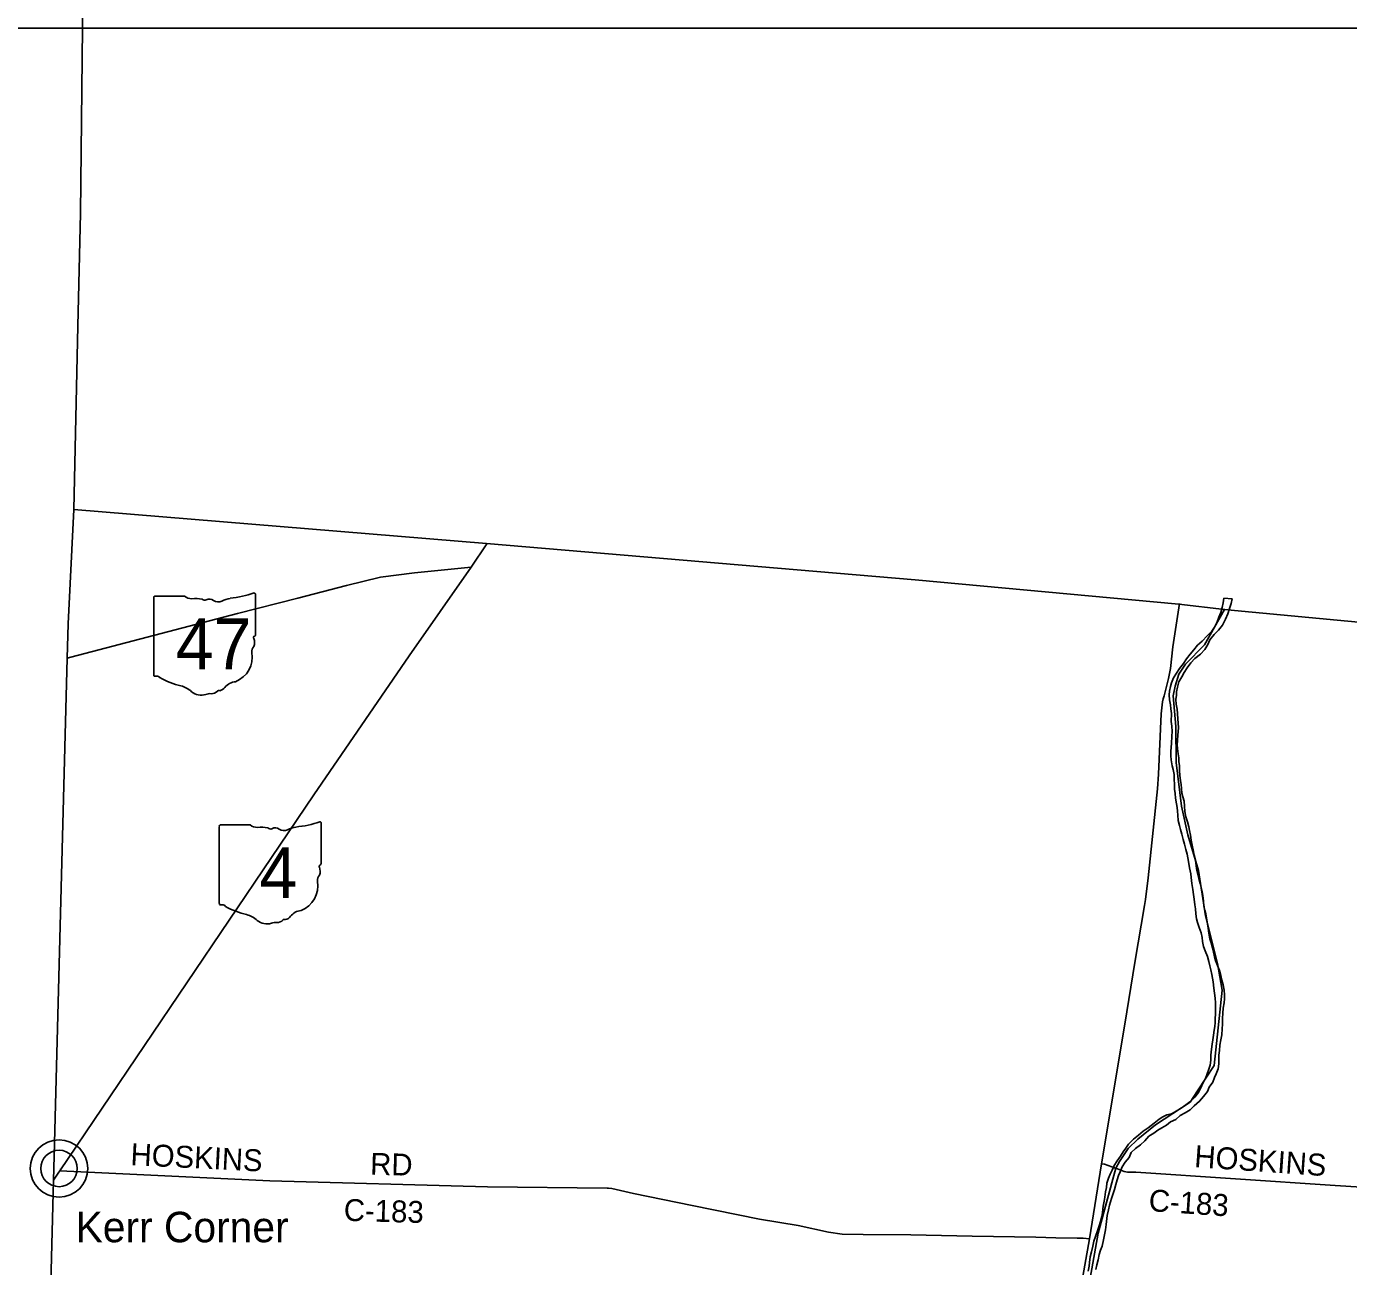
# Model space of a CAD drawing. Extents: x 1674899 to 2057726, y 653888 to 988278.
# Drawn here: x 1759512 to 1777590, y 880687 to 897649 of the extents above; entities that cross this region are included whole.
import ezdxf

# ---------------------------------------------------------------- set-up
doc = ezdxf.new("R2010")
doc.units = 0
for name, color, linetype in [('GM_X_Adjacent_County', 7, 'Continuous'), ('GM_X_County', 7, 'Continuous'), ('GM_X_County_Road', 7, 'Continuous'), ('GM_X_County_Road_Text', 7, 'Continuous'), ('GM_X_Major_River', 7, 'Continuous'), ('GM_X_State_Location', 7, 'Continuous'), ('GM_X_State_Route', 7, 'Continuous'), ('GM_X_State_Shield', 7, 'Continuous'), ('GM_X_Township', 7, 'Continuous'), ('GM_X_Unincorporated', 7, 'Continuous'), ('GM_X_Unincorporated_Location', 7, 'Continuous'), ('GM_X_Unincorporated_Text', 7, 'Continuous'), ('SH_Named_Boundary', 7, 'Continuous')]:
    doc.layers.add(name, color=color, linetype=linetype)

msp = doc.modelspace()

# ---------------------------------------------------------------- linework, layer by layer
at = {"layer": 'GM_X_Adjacent_County'}
for points in [[(1758493, 914019), (1759934, 914025), (1760358, 914021), (1760364, 911751), (1760364, 911476), (1760357, 909471), (1760334, 904783), (1760318, 901515), (1760281, 898058), (1760249, 895094), (1760215, 893547), (1760161, 891042), (1760084, 889480), (1760071, 889009), (1759886, 882027), (1759881, 881868), (1759795, 878524), (1759745, 876009), (1759690, 868390), (1759631, 865937), (1759615, 862978)], [(1778209, 889456), (1776032, 889658), (1775894, 889674), (1775269, 889747), (1771666, 890080), (1765804, 890577), (1760161, 891042), (1760215, 893547), (1760249, 895094), (1760281, 898058), (1760318, 901515), (1760334, 904783), (1760357, 909471), (1760364, 911476), (1760364, 911751), (1760358, 914021), (1759934, 914025), (1758493, 914019)]]:
    msp.add_lwpolyline(points, dxfattribs=at)
at = {"layer": 'GM_X_County'}
msp.add_lwpolyline([(1759615, 862978), (1759631, 865937), (1759690, 868390), (1759745, 876009), (1759795, 878524), (1759881, 881868), (1759886, 882027), (1760071, 889009), (1760084, 889480), (1760161, 891042), (1765804, 890577), (1771666, 890080), (1775269, 889747), (1775894, 889674), (1776032, 889658), (1778209, 889456)], dxfattribs=at)
at = {"layer": 'GM_X_County_Road'}
for points in [[(1774211, 882090), (1774252, 882089), (1774404, 882033)], [(1774404, 882033), (1774406, 882032), (1774523, 881989), (1774565, 881978), (1774598, 881976), (1774681, 881977), (1777408, 881796), (1778560, 881723), (1779427, 881668), (1779984, 881633), (1780423, 881605), (1780749, 881582)], [(1759969, 881997), (1762841, 881858), (1765814, 881778), (1767451, 881759), (1767471, 881758), (1767516, 881753), (1767813, 881684), (1768617, 881522), (1769536, 881337), (1770062, 881247), (1770477, 881159), (1770666, 881130), (1770953, 881125), (1771606, 881121), (1772443, 881104), (1773313, 881088), (1773587, 881081), (1773877, 881076), (1773962, 881074), (1774048, 881064)]]:
    msp.add_lwpolyline(points, dxfattribs=at)
at = {"layer": 'GM_X_Major_River'}
msp.add_line((1775884, 889829), (1775997, 889820), dxfattribs=at)
for points in [[(1775884, 889829), (1775875, 889767), (1775863, 889701), (1775842, 889635), (1775817, 889569), (1775795, 889507), (1775764, 889444), (1775720, 889378), (1775655, 889313), (1775588, 889243), (1775526, 889184), (1775473, 889124), (1775423, 889063), (1775376, 888999), (1775334, 888934), (1775279, 888868), (1775236, 888803), (1775196, 888737), (1775167, 888671), (1775155, 888619), (1775142, 888557), (1775137, 888507), (1775141, 888439), (1775154, 888371), (1775161, 888313), (1775167, 888250), (1775166, 888144), (1775173, 888080), (1775176, 888006), (1775175, 887940), (1775170, 887840), (1775166, 887790), (1775159, 887730), (1775159, 887672), (1775166, 887618), (1775177, 887537), (1775193, 887487), (1775204, 887415), (1775207, 887347), (1775208, 887283), (1775212, 887215), (1775217, 887156), (1775222, 887092), (1775237, 887016), (1775247, 886966), (1775252, 886914), (1775256, 886862), (1775261, 886789), (1775276, 886721), (1775290, 886667), (1775309, 886601), (1775330, 886530), (1775347, 886466), (1775363, 886392), (1775382, 886327), (1775391, 886275), (1775407, 886199), (1775416, 886141), (1775433, 886057), (1775438, 886006), (1775448, 885928), (1775459, 885846), (1775470, 885776), (1775481, 885712), (1775490, 885633), (1775496, 885579), (1775501, 885511), (1775512, 885445), (1775524, 885391), (1775549, 885324), (1775574, 885252), (1775587, 885188), (1775595, 885131), (1775608, 885063), (1775629, 885005), (1775659, 884927), (1775678, 884858), (1775693, 884802), (1775707, 884746), (1775720, 884682), (1775729, 884631), (1775737, 884581), (1775746, 884493), (1775764, 884357), (1775770, 884294), (1775771, 884226), (1775772, 884142), (1775767, 884076), (1775765, 884026), (1775760, 883972), (1775754, 883918), (1775745, 883852), (1775734, 883788), (1775724, 883730), (1775715, 883658), (1775708, 883580), (1775707, 883508), (1775699, 883442), (1775678, 883388), (1775657, 883322), (1775635, 883257)], [(1775997, 889820), (1775985, 889754), (1775964, 889688), (1775940, 889616), (1775905, 889542), (1775868, 889461), (1775812, 889393), (1775753, 889330), (1775692, 889260), (1775664, 889194), (1775623, 889129), (1775564, 889063), (1775490, 889002), (1775433, 888943), (1775381, 888875), (1775342, 888811), (1775310, 888752), (1775269, 888686), (1775250, 888612), (1775236, 888550), (1775235, 888500), (1775229, 888444), (1775234, 888380), (1775247, 888310), (1775253, 888252), (1775256, 888173), (1775261, 888123), (1775264, 888055), (1775258, 888003), (1775257, 887953), (1775253, 887883), (1775248, 887821), (1775251, 887771), (1775261, 887701), (1775268, 887647), (1775270, 887594), (1775277, 887534), (1775280, 887476), (1775281, 887402), (1775293, 887336), (1775302, 887282), (1775306, 887226), (1775311, 887163), (1775322, 887113), (1775340, 887053), (1775345, 886985), (1775350, 886909), (1775365, 886836), (1775389, 886768), (1775404, 886702), (1775413, 886652), (1775427, 886585), (1775438, 886519), (1775453, 886449), (1775464, 886385), (1775480, 886312), (1775499, 886244), (1775504, 886170), (1775517, 886106), (1775529, 886049), (1775542, 885993), (1775559, 885927), (1775573, 885873), (1775586, 885817), (1775596, 885764), (1775605, 885686), (1775612, 885616), (1775623, 885562), (1775637, 885510), (1775646, 885451), (1775663, 885375), (1775671, 885313), (1775678, 885245), (1775695, 885170), (1775712, 885116), (1775730, 885048), (1775745, 884988), (1775758, 884925), (1775772, 884873), (1775826, 884736), (1775845, 884666), (1775859, 884606), (1775876, 884538), (1775887, 884469), (1775892, 884403), (1775892, 884349), (1775887, 884295), (1775877, 884219), (1775872, 884153), (1775867, 884079), (1775866, 884001), (1775862, 883937), (1775857, 883857), (1775842, 883789), (1775829, 883713), (1775823, 883641), (1775818, 883577), (1775815, 883513), (1775815, 883459), (1775806, 883391), (1775781, 883325)], [(1775781, 883325), (1775757, 883271), (1775732, 883207), (1775685, 883140), (1775661, 883080), (1775606, 883011), (1775552, 882947), (1775481, 882884), (1775423, 882832), (1775354, 882791), (1775286, 882752), (1775228, 882700), (1775157, 882665), (1775101, 882621), (1775035, 882582), (1774981, 882551), (1774926, 882513), (1774860, 882472), (1774803, 882408), (1774745, 882351), (1774678, 882302), (1774618, 882246), (1774591, 882180), (1774537, 882115), (1774496, 882051), (1774466, 881984), (1774445, 881932), (1774428, 881872), (1774406, 881808), (1774391, 881742), (1774369, 881684), (1774348, 881618), (1774323, 881528), (1774308, 881463), (1774291, 881387), (1774276, 881261), (1774265, 881189), (1774251, 881119), (1774238, 881053), (1774219, 880965), (1774199, 880911), (1774182, 880851), (1774165, 880779), (1774147, 880711), (1774134, 880645)], [(1775635, 883257), (1775602, 883203), (1775570, 883131), (1775537, 883067), (1775486, 883002), (1775418, 882940), (1775366, 882899), (1775301, 882854), (1775233, 882810), (1775169, 882777), (1775103, 882760), (1775050, 882734), (1775000, 882701), (1774930, 882647), (1774851, 882584), (1774783, 882537), (1774716, 882483), (1774648, 882430), (1774581, 882361), (1774543, 882307), (1774506, 882255), (1774470, 882198), (1774427, 882132), (1774387, 882068), (1774356, 882005), (1774331, 881951), (1774309, 881897), (1774286, 881829), (1774278, 881767), (1774267, 881707), (1774258, 881637), (1774246, 881583), (1774235, 881511), (1774226, 881427), (1774215, 881373), (1774199, 881304), (1774178, 881246), (1774157, 881176), (1774129, 881098), (1774108, 881032), (1774095, 880964), (1774077, 880886), (1774056, 880818), (1774047, 880744), (1774041, 880690), (1774028, 880625)]]:
    msp.add_lwpolyline(points, dxfattribs=at)
at = {"layer": 'GM_X_State_Route'}
for points in [[(1759881, 881868), (1759956, 881980), (1759969, 881997), (1763443, 887141), (1764744, 889038), (1765591, 890255), (1765808, 890573)], [(1760071, 889009), (1760118, 889022), (1762397, 889618), (1763225, 889831), (1763889, 890004), (1764355, 890118), (1764820, 890175), (1765591, 890255)], [(1773882, 880140), (1774048, 881064), (1774211, 882090), (1774530, 884003), (1774667, 884846), (1774801, 885624), (1774814, 885707), (1774851, 886003), (1774976, 887219), (1774992, 887423), (1775028, 888248), (1775030, 888289), (1775035, 888331), (1775040, 888372), (1775048, 888413), (1775057, 888454), (1775067, 888494), (1775128, 888732), (1775139, 888776), (1775154, 888865), (1775187, 889163), (1775276, 889757)]]:
    msp.add_lwpolyline(points, dxfattribs=at)
at = {"layer": 'GM_X_State_Shield'}
for p, q in [((1761252, 889837), (1761252, 888780)), ((1761673, 889855), (1761266, 889855)), ((1762644, 889328), (1762644, 889881)), ((1762644, 889329), (1762644, 889328)), ((1762571, 886727), (1762163, 886727)), ((1763542, 886200), (1763542, 886753)), ((1762149, 886708), (1762149, 885652)), ((1763542, 886200), (1763542, 886200))]:
    msp.add_line(p, q, dxfattribs=at)
for centre, radius, start, end in [((1761268, 889839), 16.1, 98.1301, 188.1301), ((1761770, 889978), 156, 231.6195, 271.1119), ((1761822, 889262), 562, 80.4867, 94.9883), ((1761950, 889845), 45.1, 219.7921, 297.1024), ((1762016, 889722), 93.8, 54.4667, 119.1411), ((1762137, 889890), 113, 233.8562, 294.8282), ((1762336, 889532), 297, 97.3462, 120.7689), ((1762148, 891296), 1476, 275.8445, 288.9065), ((1762629, 889883), 15.5, 351.8621, 97.738), ((1762640, 889288), 24, 107.944, 210.337), ((1762488, 889218), 144, 340.033, 23.6496), ((1762628, 889326), 16.6, 289.6038, 7.7341), ((1762231, 889027), 369, 292.3089, 8.9858), ((1762700, 889097), 105, 136.8065, 186.9296), ((1761268, 888778), 16.3, 171.9584, 258.3066), ((1761270, 888886), 124, 267.339, 280.6039), ((1761296, 888719), 44.8, 29.7484, 93.2717), ((1761861, 889669), 1066, 240.4129, 257.1985), ((1761543, 888305), 334, 47.1842, 75.836), ((1761904, 888714), 212, 230.7004, 286.2918), ((1762042, 888635), 113, 268.777, 315.5493), ((1762144, 888533), 31.8, 65.7517, 132.6484), ((1762130, 888678), 119, 282.8732, 323.2771), ((1762387, 888484), 202, 94.4031, 142.5768), ((1762026, 888349), 174, 85.6951, 111.2099), ((1762165, 886711), 16.1, 98.1301, 188.1301), ((1762668, 886849), 156, 231.6195, 271.1119), ((1763046, 888167), 1476, 275.8445, 288.9065), ((1763526, 886755), 15.5, 351.8621, 97.738), ((1762720, 886133), 562, 80.4867, 94.9883), ((1762847, 886716), 45.1, 219.7921, 297.1024), ((1762914, 886594), 93.8, 54.4667, 119.1411), ((1763035, 886762), 113, 233.8562, 294.8282), ((1763234, 886404), 297, 97.3462, 120.7689), ((1763538, 886159), 24, 107.944, 210.337), ((1763525, 886198), 16.6, 289.6038, 7.7341), ((1763597, 885969), 105, 136.8065, 186.9296), ((1763385, 886090), 144, 340.033, 23.6496), ((1763128, 885898), 369, 292.3089, 8.9858), ((1762166, 885649), 16.3, 171.9584, 258.3066), ((1762168, 885758), 124, 267.339, 280.6039), ((1762193, 885591), 44.8, 29.7484, 93.2717), ((1762759, 886540), 1066, 240.4129, 257.1985), ((1762441, 885177), 334, 47.1842, 75.836), ((1763028, 885549), 119, 282.8732, 323.2771), ((1763284, 885355), 202, 94.4031, 142.5768), ((1762802, 885586), 212, 230.7004, 286.2918), ((1762924, 885220), 174, 85.6951, 111.2099), ((1762939, 885506), 113, 268.777, 315.5493), ((1763041, 885404), 31.8, 65.7517, 132.6484)]:
    msp.add_arc(centre, radius, start, end, dxfattribs=at)
at = {"layer": 'GM_X_Township'}
for points in [[(1759795, 878524), (1759881, 881868), (1759886, 882027), (1760071, 889009), (1760084, 889480), (1760161, 891042), (1765804, 890577), (1771666, 890080), (1775269, 889747), (1775894, 889674), (1775618, 889192), (1775360, 888928), (1775271, 888791), (1775219, 888624), (1775193, 888494), (1775230, 888073), (1775234, 887582), (1775307, 886986), (1775391, 886594), (1775537, 886105), (1775636, 885483), (1775797, 884834), (1775862, 884465), (1775753, 883439), (1775526, 883091), (1775424, 882934), (1774948, 882624), (1774707, 882427), (1774578, 882303), (1774456, 882123), (1774406, 882032), (1774167, 881144), (1774059, 880530)], [(1774059, 880530), (1774167, 881144), (1774406, 882032), (1774456, 882123), (1774578, 882303), (1774707, 882427), (1774948, 882624), (1775424, 882934), (1775526, 883091), (1775753, 883439), (1775862, 884465), (1775797, 884834), (1775636, 885483), (1775537, 886105), (1775391, 886594), (1775307, 886986), (1775234, 887582), (1775230, 888073), (1775193, 888494), (1775219, 888624), (1775271, 888791), (1775360, 888928), (1775618, 889192), (1775894, 889674), (1776032, 889658), (1778209, 889456)]]:
    msp.add_lwpolyline(points, dxfattribs=at)
at = {"layer": 'GM_X_Unincorporated'}
for radius in [393, 249]:
    msp.add_circle((1759958, 882028), radius, dxfattribs=at)
at = {"layer": 'GM_X_Unincorporated_Location'}
msp.add_line((1759958, 882028), (1759958, 882028), dxfattribs=at)
at = {"layer": 'SH_Named_Boundary'}
msp.add_lwpolyline([(1741253, 762626), (1916253, 762626), (1916253, 897626), (1741253, 897626)], close=True, dxfattribs=at)

# ---------------------------------------------------------------- texts
at = {"layer": 'GM_X_County_Road_Text'}
for s, rotation, p in [('HOSKINS', 357.1459, (1760930, 882075)), ('RD', 358.5175, (1764209, 881943)), ('HOSKINS', 356.0279, (1775474, 882048)), ('C-183', 356.1308, (1774850, 881446)), ('C-183', 358.3476, (1763848, 881313))]:
    msp.add_text(s, height=300, rotation=rotation, dxfattribs=at).set_placement(p)
at = {"layer": 'GM_X_State_Location'}
for s, p in [('47', (1761680, 889165)), ('4', (1762679, 886037))]:
    msp.add_text(s, height=1, rotation=0, dxfattribs=at).set_placement(p)
for s, p in [('s', (1761932, 889238)), ('r', (1761932, 889238)), ('s', (1762830, 886110)), ('r', (1762830, 886110))]:
    msp.add_text(s, height=1, dxfattribs=at).set_placement(p)
at = {"layer": 'GM_X_State_Shield'}
for s, height, p in [('47', 696.1, (1761554, 888855)), ('4', 696, (1762698, 885726))]:
    msp.add_text(s, height=height, dxfattribs=at).set_placement(p)
at = {"layer": 'GM_X_Unincorporated_Text'}
msp.add_text('Kerr Corner', height=417, rotation=0, dxfattribs=at).set_placement((1760184, 881019))

doc.saveas('drawing.dxf')
